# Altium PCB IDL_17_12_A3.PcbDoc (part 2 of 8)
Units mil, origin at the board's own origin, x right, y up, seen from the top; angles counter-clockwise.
Board outline 5119.97 x 10350 mil, 6 copper layers (Top Signal, 3.3 Volt, GND, 5 Volt, Split Plane, Bot Signal), stack 66.2 mil thick; 510 components, 178 nets, 2317 pads, 385 vias.
Unrouted connection lines stored in the file: 1.
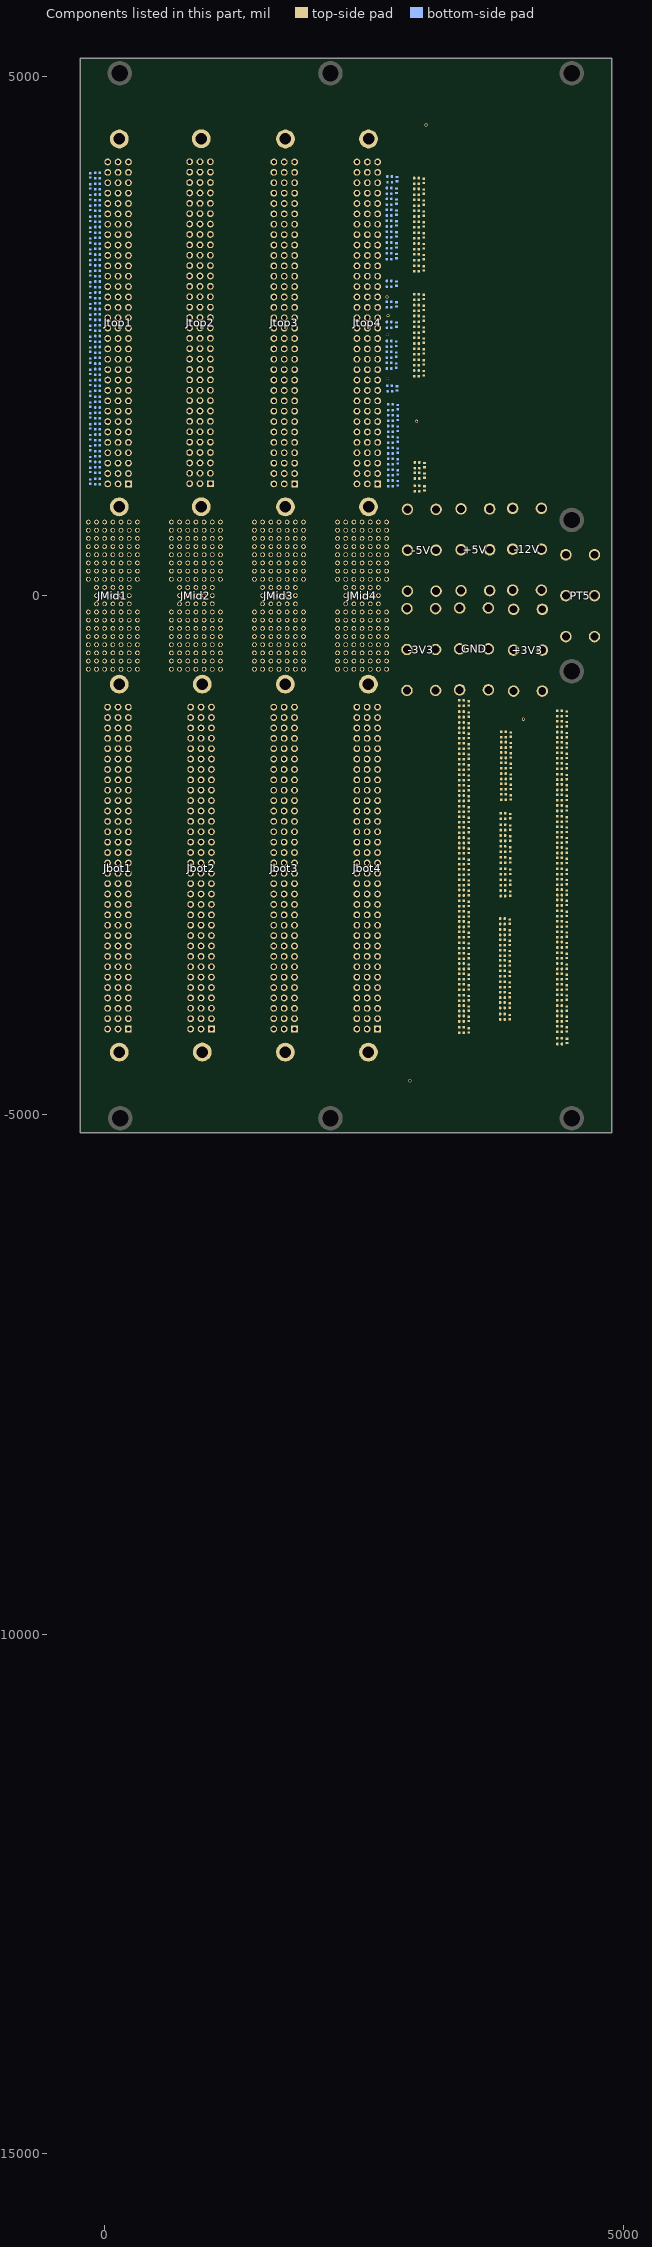
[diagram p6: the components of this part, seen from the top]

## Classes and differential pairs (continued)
component class IDL_17_12_TerB50: CRB_IDL_17_12_TerB50 R1RB_IDL_17_12_TerB50 R2RB_IDL_17_12_TerB50
component class IDL_17_12_TerB51: CRB_IDL_17_12_TerB51 R1RB_IDL_17_12_TerB51 R2RB_IDL_17_12_TerB51
component class IDL_17_12_TerB52: CRB_IDL_17_12_TerB52 R1RB_IDL_17_12_TerB52 R2RB_IDL_17_12_TerB52
component class IDL_17_12_TerB53: CRB_IDL_17_12_TerB53 R1RB_IDL_17_12_TerB53 R2RB_IDL_17_12_TerB53
component class IDL_17_12_TerB54: CRB_IDL_17_12_TerB54 R1RB_IDL_17_12_TerB54 R2RB_IDL_17_12_TerB54
component class IDL_17_12_TerB55: CRB_IDL_17_12_TerB55 R1RB_IDL_17_12_TerB55 R2RB_IDL_17_12_TerB55
component class IDL_17_12_TerB56: CRB_IDL_17_12_TerB56 R1RB_IDL_17_12_TerB56 R2RB_IDL_17_12_TerB56
component class IDL_17_12_TerB57: CRB_IDL_17_12_TerB57 R1RB_IDL_17_12_TerB57 R2RB_IDL_17_12_TerB57
component class IDL_17_12_TerB58: CRB_IDL_17_12_TerB58 R1RB_IDL_17_12_TerB58 R2RB_IDL_17_12_TerB58
component class IDL_17_12_TerB59: CRB_IDL_17_12_TerB59 R1RB_IDL_17_12_TerB59 R2RB_IDL_17_12_TerB59
component class IDL_17_12_TerB60: CRB_IDL_17_12_TerB60 R1RB_IDL_17_12_TerB60 R2RB_IDL_17_12_TerB60
component class IDL_17_12_TerB61: CRB_IDL_17_12_TerB61 R1RB_IDL_17_12_TerB61 R2RB_IDL_17_12_TerB61
component class IDL_17_12_TerB62: CRB_IDL_17_12_TerB62 R1RB_IDL_17_12_TerB62 R2RB_IDL_17_12_TerB62
component class IDL_17_12_TerB63: CRB_IDL_17_12_TerB63 R1RB_IDL_17_12_TerB63 R2RB_IDL_17_12_TerB63
component class IDL_17_12_TerB64: CRB_IDL_17_12_TerB64 R1RB_IDL_17_12_TerB64 R2RB_IDL_17_12_TerB64
component class IDL_17_12_TerB65: CRB_IDL_17_12_TerB65 R1RB_IDL_17_12_TerB65 R2RB_IDL_17_12_TerB65
component class IDL_17_12_TerB66: CRB_IDL_17_12_TerB66 R1RB_IDL_17_12_TerB66 R2RB_IDL_17_12_TerB66
component class IDL_17_12_TerB67: CRB_IDL_17_12_TerB67 R1RB_IDL_17_12_TerB67 R2RB_IDL_17_12_TerB67
component class IDL_17_12_TerB68: CRB_IDL_17_12_TerB68 R1RB_IDL_17_12_TerB68 R2RB_IDL_17_12_TerB68
component class IDL_17_12_TerB69: CRB_IDL_17_12_TerB69 R1RB_IDL_17_12_TerB69 R2RB_IDL_17_12_TerB69
component class IDL_17_12_TerB70: CRB_IDL_17_12_TerB70 R1RB_IDL_17_12_TerB70 R2RB_IDL_17_12_TerB70
component class IDL_17_12_TerB71: CRB_IDL_17_12_TerB71 R1RB_IDL_17_12_TerB71 R2RB_IDL_17_12_TerB71
component class IDL_17_12_TerB72: CRB_IDL_17_12_TerB72 R1RB_IDL_17_12_TerB72 R2RB_IDL_17_12_TerB72
component class IDL_17_12_TerB73: CRB_IDL_17_12_TerB73 R1RB_IDL_17_12_TerB73 R2RB_IDL_17_12_TerB73
component class IDL_17_12_TerB74: CRB_IDL_17_12_TerB74 R1RB_IDL_17_12_TerB74 R2RB_IDL_17_12_TerB74
component class IDL_17_12_TerB75: CRB_IDL_17_12_TerB75 R1RB_IDL_17_12_TerB75 R2RB_IDL_17_12_TerB75
component class IDL_17_12_TerB76: CRB_IDL_17_12_TerB76 R1RB_IDL_17_12_TerB76 R2RB_IDL_17_12_TerB76
component class IDL_17_12_TerB77: CRB_IDL_17_12_TerB77 R1RB_IDL_17_12_TerB77 R2RB_IDL_17_12_TerB77
component class IDL_17_12_TerB78: CRB_IDL_17_12_TerB78 R1RB_IDL_17_12_TerB78 R2RB_IDL_17_12_TerB78
component class IDL_17_12_TerB79: CRB_IDL_17_12_TerB79 R1RB_IDL_17_12_TerB79 R2RB_IDL_17_12_TerB79
component class IDL_17_12_TerB80: CRB_IDL_17_12_TerB80 R1RB_IDL_17_12_TerB80 R2RB_IDL_17_12_TerB80
component class IDL_17_12_TerB81: CRB_IDL_17_12_TerB81 R1RB_IDL_17_12_TerB81 R2RB_IDL_17_12_TerB81
component class IDL_17_12_TerB82: CRB_IDL_17_12_TerB82 R1RB_IDL_17_12_TerB82 R2RB_IDL_17_12_TerB82
component class IDL_17_12_TerB83: CRB_IDL_17_12_TerB83 R1RB_IDL_17_12_TerB83 R2RB_IDL_17_12_TerB83
component class IDL_17_12_TerB84: CRB_IDL_17_12_TerB84 R1RB_IDL_17_12_TerB84 R2RB_IDL_17_12_TerB84
component class IDL_17_12_TerB85: CRB_IDL_17_12_TerB85 R1RB_IDL_17_12_TerB85 R2RB_IDL_17_12_TerB85
component class IDL_17_12_TerB86: CRB_IDL_17_12_TerB86 R1RB_IDL_17_12_TerB86 R2RB_IDL_17_12_TerB86
component class IDL_17_12_TerB87: CRB_IDL_17_12_TerB87 R1RB_IDL_17_12_TerB87 R2RB_IDL_17_12_TerB87
component class IDL_17_12_TerB88: CRB_IDL_17_12_TerB88 R1RB_IDL_17_12_TerB88 R2RB_IDL_17_12_TerB88
component class IDL_17_12_Top: +3V3 +5V -3V3 -5V -12V GND PT5
net class JB[1..89]: JB1 JB2 JB3 JB4 JB5 JB6 JB7 JB8 JB9 JB10 JB11 JB12 JB13 JB14 JB15 JB16 JB17 JB18 JB19 JB20 JB21 JB22 JB23 JB24 JB25 JB26 JB27 JB28 JB29 JB30 JB31 JB32 JB33 JB34 JB35 JB36 JB37 JB38 JB39 JB40 JB41 JB42 JB43 JB44 JB45 JB46 JB47 JB48 JB49 JB50 JB51 JB52 JB53 JB54 JB55 JB56 JB57 JB58 JB59 JB60 JB61 JB62 JB63 JB64 JB65 JB66 JB67 JB68 JB69 JB70 JB71 JB72 JB73 JB74 JB75 JB76 JB77 JB78 JB79 JB80 JB81 JB82 JB83 JB84 JB85 JB86 JB87 JB88 JB89
net class JT[1..72]: JT1 JT2 JT3 JT4 JT5 JT6 JT7 JT8 JT9 JT10 JT11 JT12 JT13 JT14 JT15 JT16 JT17 JT18 JT19 JT20 JT21 JT22 JT23 JT24 JT25 JT26 JT27 JT28 JT29 JT30 JT31 JT32 JT33 JT34 JT35 JT36 JT37 JT38 JT39 JT40 JT41 JT42 JT43 JT44 JT45 JT46 JT47 JT48 JT49 JT50 JT51 JT52 JT53 JT54 JT55 JT56 JT57 JT58 JT59 JT60 JT61 JT62 JT63 JT64 JT65 JT66 JT67 JT68 JT69 JT70 JT71 JT72
channel class IDL_17_12_TerA: IDL_17_12_TerA1 IDL_17_12_TerA2 IDL_17_12_TerA3 IDL_17_12_TerA4 IDL_17_12_TerA5 IDL_17_12_TerA6 IDL_17_12_TerA7 IDL_17_12_TerA8 IDL_17_12_TerA9 IDL_17_12_TerA10 IDL_17_12_TerA11 IDL_17_12_TerA12 IDL_17_12_TerA13 IDL_17_12_TerA14 IDL_17_12_TerA15 IDL_17_12_TerA16 IDL_17_12_TerA17 IDL_17_12_TerA18 IDL_17_12_TerA19 IDL_17_12_TerA20 IDL_17_12_TerA21 IDL_17_12_TerA22 IDL_17_12_TerA23 IDL_17_12_TerA24 IDL_17_12_TerA25 IDL_17_12_TerA26 IDL_17_12_TerA27 IDL_17_12_TerA28 IDL_17_12_TerA29 IDL_17_12_TerA30 IDL_17_12_TerA31 IDL_17_12_TerA32 IDL_17_12_TerA33 IDL_17_12_TerA34 IDL_17_12_TerA35 IDL_17_12_TerA36 IDL_17_12_TerA37 IDL_17_12_TerA38 IDL_17_12_TerA39 IDL_17_12_TerA40 IDL_17_12_TerA41 IDL_17_12_TerA42 IDL_17_12_TerA43 IDL_17_12_TerA44 IDL_17_12_TerA45 IDL_17_12_TerA46 IDL_17_12_TerA47 IDL_17_12_TerA48 IDL_17_12_TerA49 IDL_17_12_TerA50 IDL_17_12_TerA51 IDL_17_12_TerA52 IDL_17_12_TerA53 IDL_17_12_TerA54 IDL_17_12_TerA55 IDL_17_12_TerA56 IDL_17_12_TerA57 IDL_17_12_TerA58 IDL_17_12_TerA59 IDL_17_12_TerA60 IDL_17_12_TerA61 IDL_17_12_TerA62 IDL_17_12_TerA63 IDL_17_12_TerA64 IDL_17_12_TerA65 IDL_17_12_TerA66 IDL_17_12_TerA67 IDL_17_12_TerA68 IDL_17_12_TerA69 IDL_17_12_TerA70 IDL_17_12_TerA71
channel class IDL_17_12_TerB: IDL_17_12_TerB1 IDL_17_12_TerB2 IDL_17_12_TerB3 IDL_17_12_TerB4 IDL_17_12_TerB5 IDL_17_12_TerB6 IDL_17_12_TerB7 IDL_17_12_TerB8 IDL_17_12_TerB9 IDL_17_12_TerB10 IDL_17_12_TerB11 IDL_17_12_TerB12 IDL_17_12_TerB13 IDL_17_12_TerB14 IDL_17_12_TerB15 IDL_17_12_TerB16 IDL_17_12_TerB17 IDL_17_12_TerB18 IDL_17_12_TerB19 IDL_17_12_TerB20 IDL_17_12_TerB21 IDL_17_12_TerB22 IDL_17_12_TerB23 IDL_17_12_TerB24 IDL_17_12_TerB25 IDL_17_12_TerB26 IDL_17_12_TerB27 IDL_17_12_TerB28 IDL_17_12_TerB29 IDL_17_12_TerB30 IDL_17_12_TerB31 IDL_17_12_TerB32 IDL_17_12_TerB33 IDL_17_12_TerB34 IDL_17_12_TerB35 IDL_17_12_TerB36 IDL_17_12_TerB37 IDL_17_12_TerB38 IDL_17_12_TerB39 IDL_17_12_TerB40 IDL_17_12_TerB41 IDL_17_12_TerB42 IDL_17_12_TerB43 IDL_17_12_TerB44 IDL_17_12_TerB45 IDL_17_12_TerB46 IDL_17_12_TerB47 IDL_17_12_TerB48 IDL_17_12_TerB49 IDL_17_12_TerB50 IDL_17_12_TerB51 IDL_17_12_TerB52 IDL_17_12_TerB53 IDL_17_12_TerB54 IDL_17_12_TerB55 IDL_17_12_TerB56 IDL_17_12_TerB57 IDL_17_12_TerB58 IDL_17_12_TerB59 IDL_17_12_TerB60 IDL_17_12_TerB61 IDL_17_12_TerB62 IDL_17_12_TerB63 IDL_17_12_TerB64 IDL_17_12_TerB65 IDL_17_12_TerB66 IDL_17_12_TerB67 IDL_17_12_TerB68 IDL_17_12_TerB69 IDL_17_12_TerB70 IDL_17_12_TerB71 IDL_17_12_TerB72 IDL_17_12_TerB73 IDL_17_12_TerB74 IDL_17_12_TerB75 IDL_17_12_TerB76 IDL_17_12_TerB77 IDL_17_12_TerB78 IDL_17_12_TerB79 IDL_17_12_TerB80 IDL_17_12_TerB81 IDL_17_12_TerB82 IDL_17_12_TerB83 IDL_17_12_TerB84 IDL_17_12_TerB85 IDL_17_12_TerB86 IDL_17_12_TerB87 IDL_17_12_TerB88
component class IDL_17_12_TerB89: CRB_IDL_17_12_TerB89 R1RB_IDL_17_12_TerB89 R2RB_IDL_17_12_TerB89

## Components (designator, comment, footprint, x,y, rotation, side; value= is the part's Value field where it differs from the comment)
+3V3 "*" PowerTap 3938.12,-919.16 r90 top (schematic designator PT2)
+5V "*" PowerTap 3431.95,48.27 r90 top (schematic designator PT7)
-3V3 "*" PowerTap 2911,-912.72 r90 top (schematic designator PT3)
-5V "*" PowerTap 2915.56,43.52 r90 top (schematic designator PT1)
-12V "*" PowerTap 3929.35,53.22 r90 top (schematic designator PT6)
AS "Comment" TPH0.5S 2717.58,2875.93 r0 bottom
CR_IDL_17_12_TerA1 ".1uF" CC0402N1X 2814.85,4010.34 r90 bottom (schematic designator CR)
CR_IDL_17_12_TerA2 ".1uF" CC0402N1X 2809.85,3899.1 r90 bottom (schematic designator CR)
CR_IDL_17_12_TerA3 ".1uF" CC0402N1X 2809.85,3794.1 r90 bottom (schematic designator CR)
CR_IDL_17_12_TerA4 ".1uF" CC0402N1X 2809.85,3689.1 r90 bottom (schematic designator CR)
CR_IDL_17_12_TerA5 ".1uF" CC0402N1X 2809.85,3584.1 r90 bottom (schematic designator CR)
CR_IDL_17_12_TerA6 ".1uF" CC0402N1X 2809.85,3479.1 r90 bottom (schematic designator CR)
CR_IDL_17_12_TerA7 ".1uF" CC0402N1X 2809.85,3374.1 r90 bottom (schematic designator CR)
CR_IDL_17_12_TerA8 ".1uF" CC0402N1X 2809.85,3269.1 r90 bottom (schematic designator CR)
CR_IDL_17_12_TerA9 ".1uF" CC0402N1X 2809.85,3004.1 r90 bottom (schematic designator CR)
CR_IDL_17_12_TerA10 ".1uF" CC0402N1X 2809.85,2804.1 r90 bottom (schematic designator CR)
CR_IDL_17_12_TerA11 ".1uF" CC0402N1X 2809.85,2609.1 r90 bottom (schematic designator CR)
CR_IDL_17_12_TerA12 ".1uF" CC0402N1X 2809.48,2425.89 r90 bottom (schematic designator CR)
CR_IDL_17_12_TerA13 ".1uF" CC0402N1X 2809.48,2320.89 r90 bottom (schematic designator CR)
CR_IDL_17_12_TerA14 ".1uF" CC0402N1X 2809.48,2215.89 r90 bottom (schematic designator CR)
CR_IDL_17_12_TerA15 ".1uF" CC0402N1X 2815.49,1995.95 r90 bottom (schematic designator CR)
CR_IDL_17_12_TerA16 ".1uF" CC0402N1X 2821.19,1815.25 r90 bottom (schematic designator CR)
CR_IDL_17_12_TerA17 ".1uF" CC0402N1X 2821.19,1712.25 r90 bottom (schematic designator CR)
CR_IDL_17_12_TerA18 ".1uF" CC0402N1X 2821.19,1607.25 r90 bottom (schematic designator CR)
CR_IDL_17_12_TerA19 ".1uF" CC0402N1X 2821.19,1502.25 r90 bottom (schematic designator CR)
CR_IDL_17_12_TerA20 ".1uF" CC0402N1X 2821.19,1397.25 r90 bottom (schematic designator CR)
CR_IDL_17_12_TerA21 ".1uF" CC0402N1X 2821.19,1292.25 r90 bottom (schematic designator CR)
CR_IDL_17_12_TerA22 ".1uF" CC0402N1X 2821.19,1187.25 r90 bottom (schematic designator CR)
CR_IDL_17_12_TerA23 ".1uF" CC0402N1X 2821.19,1082.25 r90 bottom (schematic designator CR)
CR_IDL_17_12_TerA24 ".1uF" CC0402N1X 3073.37,3994.79 r90 top (schematic designator CR)
CR_IDL_17_12_TerA25 ".1uF" CC0402N1X 3073.37,3889.79 r90 top (schematic designator CR)
CR_IDL_17_12_TerA26 ".1uF" CC0402N1X 3073.37,3784.79 r90 top (schematic designator CR)
CR_IDL_17_12_TerA27 ".1uF" CC0402N1X 3073.37,3679.79 r90 top (schematic designator CR)
CR_IDL_17_12_TerA28 ".1uF" CC0402N1X 3073.37,3574.79 r90 top (schematic designator CR)
CR_IDL_17_12_TerA29 ".1uF" CC0402N1X 3073.37,3469.79 r90 top (schematic designator CR)
CR_IDL_17_12_TerA30 ".1uF" CC0402N1X 3073.37,3364.79 r90 top (schematic designator CR)
CR_IDL_17_12_TerA31 ".1uF" CC0402N1X 3073.37,3259.79 r90 top (schematic designator CR)
CR_IDL_17_12_TerA32 ".1uF" CC0402N1X 3073.37,3151.79 r90 top (schematic designator CR)
CR_IDL_17_12_TerA33 ".1uF" CC0402N1X 3073.37,2876.79 r90 top (schematic designator CR)
CR_IDL_17_12_TerA34 ".1uF" CC0402N1X 3073.37,2771.79 r90 top (schematic designator CR)
CR_IDL_17_12_TerA35 ".1uF" CC0402N1X 3073.37,2666.79 r90 top (schematic designator CR)
CR_IDL_17_12_TerA36 ".1uF" CC0402N1X 3073.37,2561.79 r90 top (schematic designator CR)
CR_IDL_17_12_TerA37 ".1uF" CC0402N1X 3073.37,2456.79 r90 top (schematic designator CR)
CR_IDL_17_12_TerA38 ".1uF" CC0402N1X 3073.37,2351.79 r90 top (schematic designator CR)
CR_IDL_17_12_TerA39 ".1uF" CC0402N1X 3073.37,2246.79 r90 top (schematic designator CR)
CR_IDL_17_12_TerA40 ".1uF" CC0402N1X 3073.37,2141.79 r90 top (schematic designator CR)
CR_IDL_17_12_TerA41 ".1uF" CC0402N1X 3079.28,1256.26 r90 top (schematic designator CR)
CR_IDL_17_12_TerA42 ".1uF" CC0402N1X 3079.28,1156.26 r90 top (schematic designator CR)
CR_IDL_17_12_TerA43 ".1uF" CC0402N1X 3079.2,1033.29 r90 top (schematic designator CR)
CR_IDL_17_12_TerA44 ".1uF" CC0402N1X -138.88,4046.37 r90 bottom (schematic designator CR)
CR_IDL_17_12_TerA45 ".1uF" CC0402N1X -138.88,3941.37 r90 bottom (schematic designator CR)
CR_IDL_17_12_TerA46 ".1uF" CC0402N1X -138.88,3836.37 r90 bottom (schematic designator CR)
CR_IDL_17_12_TerA47 ".1uF" CC0402N1X -138.88,3733.37 r90 bottom (schematic designator CR)
CR_IDL_17_12_TerA48 ".1uF" CC0402N1X -138.88,3628.37 r90 bottom (schematic designator CR)
CR_IDL_17_12_TerA49 ".1uF" CC0402N1X -138.88,3523.37 r90 bottom (schematic designator CR)
CR_IDL_17_12_TerA50 ".1uF" CC0402N1X -138.88,3418.37 r90 bottom (schematic designator CR)
CR_IDL_17_12_TerA51 ".1uF" CC0402N1X -138.88,3313.37 r90 bottom (schematic designator CR)
CR_IDL_17_12_TerA52 ".1uF" CC0402N1X -138.88,3208.37 r90 bottom (schematic designator CR)
CR_IDL_17_12_TerA53 ".1uF" CC0402N1X -138.88,3103.37 r90 bottom (schematic designator CR)
CR_IDL_17_12_TerA54 ".1uF" CC0402N1X -138.88,2998.37 r90 bottom (schematic designator CR)
CR_IDL_17_12_TerA55 ".1uF" CC0402N1X -138.88,2893.37 r90 bottom (schematic designator CR)
CR_IDL_17_12_TerA56 ".1uF" CC0402N1X -138.88,2788.37 r90 bottom (schematic designator CR)
CR_IDL_17_12_TerA57 ".1uF" CC0402N1X -138.88,2683.37 r90 bottom (schematic designator CR)
CR_IDL_17_12_TerA58 ".1uF" CC0402N1X -138.88,2578.37 r90 bottom (schematic designator CR)
CR_IDL_17_12_TerA59 ".1uF" CC0402N1X -138.88,2473.37 r90 bottom (schematic designator CR)
CR_IDL_17_12_TerA60 ".1uF" CC0402N1X -138.88,2368.37 r90 bottom (schematic designator CR)
CR_IDL_17_12_TerA61 ".1uF" CC0402N1X -138.88,2263.37 r90 bottom (schematic designator CR)
CR_IDL_17_12_TerA62 ".1uF" CC0402N1X -138.88,2155.37 r90 bottom (schematic designator CR)
CR_IDL_17_12_TerA63 ".1uF" CC0402N1X -138.88,2050.37 r90 bottom (schematic designator CR)
CR_IDL_17_12_TerA64 ".1uF" CC0402N1X -138.88,1945.37 r90 bottom (schematic designator CR)
CR_IDL_17_12_TerA65 ".1uF" CC0402N1X -138.88,1840.37 r90 bottom (schematic designator CR)
CR_IDL_17_12_TerA66 ".1uF" CC0402N1X -138.88,1735.37 r90 bottom (schematic designator CR)
CR_IDL_17_12_TerA67 ".1uF" CC0402N1X -138.88,1630.37 r90 bottom (schematic designator CR)
CR_IDL_17_12_TerA68 ".1uF" CC0402N1X -138.88,1525.37 r90 bottom (schematic designator CR)
CR_IDL_17_12_TerA69 ".1uF" CC0402N1X -138.88,1420.37 r90 bottom (schematic designator CR)
CR_IDL_17_12_TerA70 ".1uF" CC0402N1X -138.88,1315.37 r90 bottom (schematic designator CR)
CR_IDL_17_12_TerA71 ".1uF" CC0402N1X -138.88,1210.37 r90 bottom (schematic designator CR)
CR_IDL_17_12_TerA72 ".1uF" CC0402N1X -137.57,1097.91 r90 bottom (schematic designator CR)
CRB_IDL_17_12_TerB1 ".1uF" CC0402N1X 3505.91,-1038.01 r90 top (schematic designator CRB)
CRB_IDL_17_12_TerB2 ".1uF" CC0402N1X 3506.6,-1145.48 r90 top (schematic designator CRB)
CRB_IDL_17_12_TerB3 ".1uF" CC0402N1X 3506.6,-1250.48 r90 top (schematic designator CRB)
CRB_IDL_17_12_TerB4 ".1uF" CC0402N1X 3506.6,-1350.48 r90 top (schematic designator CRB)
CRB_IDL_17_12_TerB5 ".1uF" CC0402N1X 3506.6,-1450.48 r90 top (schematic designator CRB)
CRB_IDL_17_12_TerB6 ".1uF" CC0402N1X 3506.6,-1550.48 r90 top (schematic designator CRB)
CRB_IDL_17_12_TerB7 ".1uF" CC0402N1X 3506.6,-1653.48 r90 top (schematic designator CRB)
CRB_IDL_17_12_TerB8 ".1uF" CC0402N1X 3506.6,-1753.48 r90 top (schematic designator CRB)
CRB_IDL_17_12_TerB9 ".1uF" CC0402N1X 3506.6,-1853.48 r90 top (schematic designator CRB)
CRB_IDL_17_12_TerB10 ".1uF" CC0402N1X 3506.6,-1953.48 r90 top (schematic designator CRB)
CRB_IDL_17_12_TerB11 ".1uF" CC0402N1X 3506.6,-2058.48 r90 top (schematic designator CRB)
CRB_IDL_17_12_TerB12 ".1uF" CC0402N1X 3506.6,-2158.48 r90 top (schematic designator CRB)
CRB_IDL_17_12_TerB13 ".1uF" CC0402N1X 3506.6,-2258.48 r90 top (schematic designator CRB)
CRB_IDL_17_12_TerB14 ".1uF" CC0402N1X 3506.6,-2358.48 r90 top (schematic designator CRB)
CRB_IDL_17_12_TerB15 ".1uF" CC0402N1X 3506.6,-2458.48 r90 top (schematic designator CRB)
CRB_IDL_17_12_TerB16 ".1uF" CC0402N1X 3506.6,-2563.48 r90 top (schematic designator CRB)
CRB_IDL_17_12_TerB17 ".1uF" CC0402N1X 3506.6,-2663.48 r90 top (schematic designator CRB)
CRB_IDL_17_12_TerB18 ".1uF" CC0402N1X 3506.6,-2763.48 r90 top (schematic designator CRB)
CRB_IDL_17_12_TerB19 ".1uF" CC0402N1X 3506.6,-2863.48 r90 top (schematic designator CRB)
CRB_IDL_17_12_TerB20 ".1uF" CC0402N1X 3506.6,-2968.48 r90 top (schematic designator CRB)
CRB_IDL_17_12_TerB21 ".1uF" CC0402N1X 3506.6,-3068.48 r90 top (schematic designator CRB)
CRB_IDL_17_12_TerB22 ".1uF" CC0402N1X 3506.6,-3166.48 r90 top (schematic designator CRB)
CRB_IDL_17_12_TerB23 ".1uF" CC0402N1X 3506.6,-3266.48 r90 top (schematic designator CRB)
CRB_IDL_17_12_TerB24 ".1uF" CC0402N1X 3506.6,-3371.48 r90 top (schematic designator CRB)
CRB_IDL_17_12_TerB25 ".1uF" CC0402N1X 3506.6,-3471.48 r90 top (schematic designator CRB)
CRB_IDL_17_12_TerB26 ".1uF" CC0402N1X 3506.6,-3571.48 r90 top (schematic designator CRB)
CRB_IDL_17_12_TerB27 ".1uF" CC0402N1X 3506.6,-3671.48 r90 top (schematic designator CRB)
CRB_IDL_17_12_TerB28 ".1uF" CC0402N1X 3506.6,-3771.48 r90 top (schematic designator CRB)
CRB_IDL_17_12_TerB29 ".1uF" CC0402N1X 3506.6,-3876.48 r90 top (schematic designator CRB)
CRB_IDL_17_12_TerB30 ".1uF" CC0402N1X 3506.6,-3976.48 r90 top (schematic designator CRB)
CRB_IDL_17_12_TerB31 ".1uF" CC0402N1X 3506.6,-4076.48 r90 top (schematic designator CRB)
CRB_IDL_17_12_TerB32 ".1uF" CC0402N1X 3506.2,-4185.54 r90 top (schematic designator CRB)
CRB_IDL_17_12_TerB33 ".1uF" CC0402N1X 3910.55,-1339.06 r90 top (schematic designator CRB)
CRB_IDL_17_12_TerB34 ".1uF" CC0402N1X 3910.55,-1439.06 r90 top (schematic designator CRB)
CRB_IDL_17_12_TerB35 ".1uF" CC0402N1X 3910.55,-1539.06 r90 top (schematic designator CRB)
CRB_IDL_17_12_TerB36 ".1uF" CC0402N1X 3910.55,-1639.06 r90 top (schematic designator CRB)
CRB_IDL_17_12_TerB37 ".1uF" CC0402N1X 3910.55,-1742.06 r90 top (schematic designator CRB)
CRB_IDL_17_12_TerB38 ".1uF" CC0402N1X 3910.55,-1842.06 r90 top (schematic designator CRB)
CRB_IDL_17_12_TerB39 ".1uF" CC0402N1X 3910.55,-1942.06 r90 top (schematic designator CRB)
CRB_IDL_17_12_TerB40 ".1uF" CC0402N1X 3905.55,-2123.71 r90 top (schematic designator CRB)
CRB_IDL_17_12_TerB41 ".1uF" CC0402N1X 3905.55,-2233.71 r90 top (schematic designator CRB)
CRB_IDL_17_12_TerB42 ".1uF" CC0402N1X 3905.55,-2338.71 r90 top (schematic designator CRB)
CRB_IDL_17_12_TerB43 ".1uF" CC0402N1X 3905.55,-2443.71 r90 top (schematic designator CRB)
CRB_IDL_17_12_TerB44 ".1uF" CC0402N1X 3905.55,-2548.71 r90 top (schematic designator CRB)
CRB_IDL_17_12_TerB45 ".1uF" CC0402N1X 3905.55,-2658.71 r90 top (schematic designator CRB)
CRB_IDL_17_12_TerB46 ".1uF" CC0402N1X 3905.55,-2763.71 r90 top (schematic designator CRB)
CRB_IDL_17_12_TerB47 ".1uF" CC0402N1X 3905.55,-2868.71 r90 top (schematic designator CRB)
CRB_IDL_17_12_TerB48 ".1uF" CC0402N1X 3900.55,-3138.71 r90 top (schematic designator CRB)
CRB_IDL_17_12_TerB49 ".1uF" CC0402N1X 3900.55,-3243.71 r90 top (schematic designator CRB)
CRB_IDL_17_12_TerB50 ".1uF" CC0402N1X 3900.55,-3343.71 r90 top (schematic designator CRB)
CRB_IDL_17_12_TerB51 ".1uF" CC0402N1X 3900.55,-3443.71 r90 top (schematic designator CRB)
CRB_IDL_17_12_TerB52 ".1uF" CC0402N1X 3900.55,-3541.71 r90 top (schematic designator CRB)
CRB_IDL_17_12_TerB53 ".1uF" CC0402N1X 3900.55,-3641.71 r90 top (schematic designator CRB)
CRB_IDL_17_12_TerB54 ".1uF" CC0402N1X 3900.55,-3746.71 r90 top (schematic designator CRB)
CRB_IDL_17_12_TerB55 ".1uF" CC0402N1X 3900.55,-3846.71 r90 top (schematic designator CRB)
CRB_IDL_17_12_TerB56 ".1uF" CC0402N1X 3900.55,-3946.71 r90 top (schematic designator CRB)
CRB_IDL_17_12_TerB57 ".1uF" CC0402N1X 3900.51,-4057.69 r90 top (schematic designator CRB)
CRB_IDL_17_12_TerB58 ".1uF" CC0402N1X 4450.29,-1137.42 r90 top (schematic designator CRB)
CRB_IDL_17_12_TerB59 ".1uF" CC0402N1X 4450.29,-1237.42 r90 top (schematic designator CRB)
CRB_IDL_17_12_TerB60 ".1uF" CC0402N1X 4450.29,-1342.42 r90 top (schematic designator CRB)
CRB_IDL_17_12_TerB61 ".1uF" CC0402N1X 4450.29,-1442.42 r90 top (schematic designator CRB)
CRB_IDL_17_12_TerB62 ".1uF" CC0402N1X 4450.29,-1542.42 r90 top (schematic designator CRB)
CRB_IDL_17_12_TerB63 ".1uF" CC0402N1X 4450.29,-1642.42 r90 top (schematic designator CRB)
CRB_IDL_17_12_TerB64 ".1uF" CC0402N1X 4450.29,-1747.42 r90 top (schematic designator CRB)
CRB_IDL_17_12_TerB65 ".1uF" CC0402N1X 4450.29,-1847.42 r90 top (schematic designator CRB)
CRB_IDL_17_12_TerB66 ".1uF" CC0402N1X 4450.29,-1947.42 r90 top (schematic designator CRB)
CRB_IDL_17_12_TerB67 ".1uF" CC0402N1X 4450.29,-2049.42 r90 top (schematic designator CRB)
CRB_IDL_17_12_TerB68 ".1uF" CC0402N1X 4450.29,-2154.42 r90 top (schematic designator CRB)
CRB_IDL_17_12_TerB69 ".1uF" CC0402N1X 4450.29,-2254.42 r90 top (schematic designator CRB)
CRB_IDL_17_12_TerB70 ".1uF" CC0402N1X 4450.29,-2354.42 r90 top (schematic designator CRB)
CRB_IDL_17_12_TerB71 ".1uF" CC0402N1X 4450.29,-2454.42 r90 top (schematic designator CRB)
CRB_IDL_17_12_TerB72 ".1uF" CC0402N1X 4450.29,-2554.42 r90 top (schematic designator CRB)
CRB_IDL_17_12_TerB73 ".1uF" CC0402N1X 4450.29,-2659.42 r90 top (schematic designator CRB)
CRB_IDL_17_12_TerB74 ".1uF" CC0402N1X 4450.29,-2759.42 r90 top (schematic designator CRB)
CRB_IDL_17_12_TerB75 ".1uF" CC0402N1X 4450.29,-2859.42 r90 top (schematic designator CRB)
CRB_IDL_17_12_TerB76 ".1uF" CC0402N1X 4450.29,-2959.42 r90 top (schematic designator CRB)
CRB_IDL_17_12_TerB77 ".1uF" CC0402N1X 4450.29,-3064.42 r90 top (schematic designator CRB)
CRB_IDL_17_12_TerB78 ".1uF" CC0402N1X 4450.29,-3164.42 r90 top (schematic designator CRB)
CRB_IDL_17_12_TerB79 ".1uF" CC0402N1X 4450.29,-3264.42 r90 top (schematic designator CRB)
CRB_IDL_17_12_TerB80 ".1uF" CC0402N1X 4450.29,-3364.42 r90 top (schematic designator CRB)
CRB_IDL_17_12_TerB81 ".1uF" CC0402N1X 4450.29,-3469.42 r90 top (schematic designator CRB)
CRB_IDL_17_12_TerB82 ".1uF" CC0402N1X 4450.29,-3571.42 r90 top (schematic designator CRB)
CRB_IDL_17_12_TerB83 ".1uF" CC0402N1X 4450.29,-3671.42 r90 top (schematic designator CRB)
CRB_IDL_17_12_TerB84 ".1uF" CC0402N1X 4450.29,-3771.42 r90 top (schematic designator CRB)
CRB_IDL_17_12_TerB85 ".1uF" CC0402N1X 4450.29,-3871.42 r90 top (schematic designator CRB)
CRB_IDL_17_12_TerB86 ".1uF" CC0402N1X 4450.29,-3976.42 r90 top (schematic designator CRB)
CRB_IDL_17_12_TerB87 ".1uF" CC0402N1X 4450.29,-4076.42 r90 top (schematic designator CRB)
CRB_IDL_17_12_TerB88 ".1uF" CC0402N1X 4450.29,-4176.42 r90 top (schematic designator CRB)
CRB_IDL_17_12_TerB89 ".1uF" CC0402N1X 4451.51,-4288.13 r90 top (schematic designator CRB)
DTACK "Comment" TPH0.5S 2729.61,2696.1 r0 bottom
GND "*" PowerTap 3418.77,-906.67 r90 top (schematic designator PT4)
GND "Comment" TPH0.5S 4032.27,-1189.75 r0 top
GND "Comment" TPH0.5S 2938.82,-4671.37 r0 top
GND "Comment" TPH0.5S 3095.22,4533.28 r0 top
GND "Comment" TPH0.5S 3003.96,1679.15 r0 top
Jbot1 "" 0903296x825 128.26,-2623.77 r90 top
Jbot2 "" 0903296x825 928.19,-2623.35 r90 top
Jbot3 "" 0903296x825 1728.19,-2623.77 r90 top
Jbot4 "" 0903296x825 2528.19,-2623.77 r90 top
JMid1 "" "127-Pin Conncector" 74.8,23.74 r90 top
JMid2 "" "127-Pin Conncector" 874.8,23.74 r90 top
JMid3 "" "127-Pin Conncector" 1674.8,23.74 r90 top
JMid4 "" "127-Pin Conncector" 2474.8,23.74 r90 top
Jtop1 "" 0903296x825 129.28,2626.24 r90 top
Jtop2 "" 0903296x825 918.19,2628.35 r90 top
Jtop3 "" 0903296x825 1729.28,2626.24 r90 top
Jtop4 "" 0903296x825 2529.28,2626.24 r90 top
PT5 "*" PowerTap 4440.81,-394.17 r90 top
R1R_IDL_17_12_TerA1 "330R" RC0402N1R 2744.24,4036.92 r0 bottom (schematic designator R1R)
R1R_IDL_17_12_TerA2 "330R" RC0402N1R 2739.24,3925.68 r0 bottom (schematic designator R1R)
R1R_IDL_17_12_TerA3 "330R" RC0402N1R 2739.24,3820.68 r0 bottom (schematic designator R1R)
R1R_IDL_17_12_TerA4 "330R" RC0402N1R 2739.24,3715.68 r0 bottom (schematic designator R1R)
R1R_IDL_17_12_TerA5 "330R" RC0402N1R 2739.24,3610.68 r0 bottom (schematic designator R1R)
R1R_IDL_17_12_TerA6 "330R" RC0402N1R 2739.24,3505.68 r0 bottom (schematic designator R1R)
R1R_IDL_17_12_TerA7 "330R" RC0402N1R 2739.24,3400.68 r0 bottom (schematic designator R1R)
R1R_IDL_17_12_TerA8 "330R" RC0402N1R 2739.24,3295.68 r0 bottom (schematic designator R1R)
R1R_IDL_17_12_TerA9 "330R" RC0402N1R 2739.24,3030.68 r0 bottom (schematic designator R1R)
R1R_IDL_17_12_TerA10 "330R" RC0402N1R 2739.24,2830.68 r0 bottom (schematic designator R1R)
R1R_IDL_17_12_TerA11 "330R" RC0402N1R 2739.24,2635.68 r0 bottom (schematic designator R1R)
R1R_IDL_17_12_TerA12 "330R" RC0402N1R 2738.87,2452.47 r0 bottom (schematic designator R1R)
R1R_IDL_17_12_TerA13 "330R" RC0402N1R 2738.87,2347.47 r0 bottom (schematic designator R1R)
R1R_IDL_17_12_TerA14 "330R" RC0402N1R 2738.87,2242.47 r0 bottom (schematic designator R1R)
R1R_IDL_17_12_TerA15 "330R" RC0402N1R 2744.87,2022.53 r0 bottom (schematic designator R1R)
R1R_IDL_17_12_TerA16 "330R" RC0402N1R 2750.57,1841.82 r0 bottom (schematic designator R1R)
R1R_IDL_17_12_TerA17 "330R" RC0402N1R 2750.57,1738.82 r0 bottom (schematic designator R1R)
R1R_IDL_17_12_TerA18 "330R" RC0402N1R 2750.57,1633.82 r0 bottom (schematic designator R1R)
R1R_IDL_17_12_TerA19 "330R" RC0402N1R 2750.57,1528.82 r0 bottom (schematic designator R1R)
R1R_IDL_17_12_TerA20 "330R" RC0402N1R 2750.57,1423.82 r0 bottom (schematic designator R1R)
R1R_IDL_17_12_TerA21 "330R" RC0402N1R 2750.57,1318.82 r0 bottom (schematic designator R1R)
R1R_IDL_17_12_TerA22 "330R" RC0402N1R 2750.57,1213.82 r0 bottom (schematic designator R1R)
R1R_IDL_17_12_TerA23 "330R" RC0402N1R 2750.57,1108.82 r0 bottom (schematic designator R1R)
R1R_IDL_17_12_TerA24 "330R" RC0402N1R 3002.76,4021.36 r0 top (schematic designator R1R)
R1R_IDL_17_12_TerA25 "330R" RC0402N1R 3002.76,3916.36 r0 top (schematic designator R1R)
R1R_IDL_17_12_TerA26 "330R" RC0402N1R 3002.76,3811.36 r0 top (schematic designator R1R)
R1R_IDL_17_12_TerA27 "330R" RC0402N1R 3002.76,3706.36 r0 top (schematic designator R1R)
R1R_IDL_17_12_TerA28 "330R" RC0402N1R 3002.76,3601.36 r0 top (schematic designator R1R)
R1R_IDL_17_12_TerA29 "330R" RC0402N1R 3002.76,3496.36 r0 top (schematic designator R1R)
R1R_IDL_17_12_TerA30 "330R" RC0402N1R 3002.76,3391.36 r0 top (schematic designator R1R)
R1R_IDL_17_12_TerA31 "330R" RC0402N1R 3002.76,3286.36 r0 top (schematic designator R1R)
R1R_IDL_17_12_TerA32 "330R" RC0402N1R 3002.76,3178.36 r0 top (schematic designator R1R)
R1R_IDL_17_12_TerA33 "330R" RC0402N1R 3002.76,2903.36 r0 top (schematic designator R1R)
R1R_IDL_17_12_TerA34 "330R" RC0402N1R 3002.76,2798.36 r0 top (schematic designator R1R)
R1R_IDL_17_12_TerA35 "330R" RC0402N1R 3002.76,2693.36 r0 top (schematic designator R1R)
R1R_IDL_17_12_TerA36 "330R" RC0402N1R 3002.76,2588.36 r0 top (schematic designator R1R)
R1R_IDL_17_12_TerA37 "330R" RC0402N1R 3002.76,2483.36 r0 top (schematic designator R1R)
R1R_IDL_17_12_TerA38 "330R" RC0402N1R 3002.76,2378.36 r0 top (schematic designator R1R)
R1R_IDL_17_12_TerA39 "330R" RC0402N1R 3002.76,2273.36 r0 top (schematic designator R1R)
R1R_IDL_17_12_TerA40 "330R" RC0402N1R 3002.76,2168.36 r0 top (schematic designator R1R)
R1R_IDL_17_12_TerA41 "330R" RC0402N1R 3008.66,1282.84 r0 top (schematic designator R1R)
R1R_IDL_17_12_TerA42 "330R" RC0402N1R 3008.66,1182.84 r0 top (schematic designator R1R)
R1R_IDL_17_12_TerA43 "330R" RC0402N1R 3008.59,1059.87 r0 top (schematic designator R1R)
R1R_IDL_17_12_TerA44 "330R" RC0402N1R -68.27,4072.95 r180 bottom (schematic designator R1R)
R1R_IDL_17_12_TerA45 "330R" RC0402N1R -68.27,3967.95 r180 bottom (schematic designator R1R)
R1R_IDL_17_12_TerA46 "330R" RC0402N1R -68.27,3862.95 r180 bottom (schematic designator R1R)
R1R_IDL_17_12_TerA47 "330R" RC0402N1R -68.27,3759.95 r180 bottom (schematic designator R1R)
R1R_IDL_17_12_TerA48 "330R" RC0402N1R -68.27,3654.95 r180 bottom (schematic designator R1R)
R1R_IDL_17_12_TerA49 "330R" RC0402N1R -68.27,3549.95 r180 bottom (schematic designator R1R)
R1R_IDL_17_12_TerA50 "330R" RC0402N1R -68.27,3444.95 r180 bottom (schematic designator R1R)
R1R_IDL_17_12_TerA51 "330R" RC0402N1R -68.27,3339.95 r180 bottom (schematic designator R1R)
R1R_IDL_17_12_TerA52 "330R" RC0402N1R -68.27,3234.95 r180 bottom (schematic designator R1R)
R1R_IDL_17_12_TerA53 "330R" RC0402N1R -68.27,3129.95 r180 bottom (schematic designator R1R)
R1R_IDL_17_12_TerA54 "330R" RC0402N1R -68.27,3024.95 r180 bottom (schematic designator R1R)
R1R_IDL_17_12_TerA55 "330R" RC0402N1R -68.27,2919.95 r180 bottom (schematic designator R1R)
R1R_IDL_17_12_TerA56 "330R" RC0402N1R -68.27,2814.95 r180 bottom (schematic designator R1R)
R1R_IDL_17_12_TerA57 "330R" RC0402N1R -68.27,2709.95 r180 bottom (schematic designator R1R)
R1R_IDL_17_12_TerA58 "330R" RC0402N1R -68.27,2604.95 r180 bottom (schematic designator R1R)
R1R_IDL_17_12_TerA59 "330R" RC0402N1R -68.27,2499.95 r180 bottom (schematic designator R1R)
R1R_IDL_17_12_TerA60 "330R" RC0402N1R -68.27,2394.95 r180 bottom (schematic designator R1R)
R1R_IDL_17_12_TerA61 "330R" RC0402N1R -68.27,2289.95 r180 bottom (schematic designator R1R)
R1R_IDL_17_12_TerA62 "330R" RC0402N1R -68.27,2181.95 r180 bottom (schematic designator R1R)
R1R_IDL_17_12_TerA63 "330R" RC0402N1R -68.27,2076.95 r180 bottom (schematic designator R1R)
R1R_IDL_17_12_TerA64 "330R" RC0402N1R -68.27,1971.95 r180 bottom (schematic designator R1R)
R1R_IDL_17_12_TerA65 "330R" RC0402N1R -68.27,1866.95 r180 bottom (schematic designator R1R)
R1R_IDL_17_12_TerA66 "330R" RC0402N1R -68.27,1761.95 r180 bottom (schematic designator R1R)
R1R_IDL_17_12_TerA67 "330R" RC0402N1R -68.27,1656.95 r180 bottom (schematic designator R1R)
R1R_IDL_17_12_TerA68 "330R" RC0402N1R -68.27,1551.95 r180 bottom (schematic designator R1R)
R1R_IDL_17_12_TerA69 "330R" RC0402N1R -68.27,1446.95 r180 bottom (schematic designator R1R)
R1R_IDL_17_12_TerA70 "330R" RC0402N1R -68.27,1341.95 r180 bottom (schematic designator R1R)
R1R_IDL_17_12_TerA71 "330R" RC0402N1R -68.27,1236.95 r180 bottom (schematic designator R1R)
R1R_IDL_17_12_TerA72 "330R" RC0402N1R -68.28,1126.4 r180 bottom (schematic designator R1R)
R1RB_IDL_17_12_TerB1 "330R" RC0402N1R 3435.44,-1008.84 r0 top (schematic designator R1RB)
R1RB_IDL_17_12_TerB2 "330R" RC0402N1R 3436.13,-1116.31 r0 top (schematic designator R1RB)
R1RB_IDL_17_12_TerB3 "330R" RC0402N1R 3436.13,-1221.31 r0 top (schematic designator R1RB)
R1RB_IDL_17_12_TerB4 "330R" RC0402N1R 3436.13,-1321.31 r0 top (schematic designator R1RB)
R1RB_IDL_17_12_TerB5 "330R" RC0402N1R 3436.13,-1421.31 r0 top (schematic designator R1RB)
R1RB_IDL_17_12_TerB6 "330R" RC0402N1R 3436.13,-1521.31 r0 top (schematic designator R1RB)
R1RB_IDL_17_12_TerB7 "330R" RC0402N1R 3436.13,-1624.31 r0 top (schematic designator R1RB)
R1RB_IDL_17_12_TerB8 "330R" RC0402N1R 3436.13,-1724.31 r0 top (schematic designator R1RB)
R1RB_IDL_17_12_TerB9 "330R" RC0402N1R 3436.13,-1824.31 r0 top (schematic designator R1RB)
R1RB_IDL_17_12_TerB10 "330R" RC0402N1R 3436.13,-1924.31 r0 top (schematic designator R1RB)
R1RB_IDL_17_12_TerB11 "330R" RC0402N1R 3436.13,-2029.31 r0 top (schematic designator R1RB)
R1RB_IDL_17_12_TerB12 "330R" RC0402N1R 3436.13,-2129.31 r0 top (schematic designator R1RB)
R1RB_IDL_17_12_TerB13 "330R" RC0402N1R 3436.13,-2229.31 r0 top (schematic designator R1RB)
R1RB_IDL_17_12_TerB14 "330R" RC0402N1R 3436.13,-2329.31 r0 top (schematic designator R1RB)
R1RB_IDL_17_12_TerB15 "330R" RC0402N1R 3436.13,-2429.31 r0 top (schematic designator R1RB)
R1RB_IDL_17_12_TerB16 "330R" RC0402N1R 3436.13,-2534.31 r0 top (schematic designator R1RB)
R1RB_IDL_17_12_TerB17 "330R" RC0402N1R 3436.13,-2634.31 r0 top (schematic designator R1RB)
R1RB_IDL_17_12_TerB18 "330R" RC0402N1R 3436.13,-2734.31 r0 top (schematic designator R1RB)
R1RB_IDL_17_12_TerB19 "330R" RC0402N1R 3436.13,-2834.31 r0 top (schematic designator R1RB)
R1RB_IDL_17_12_TerB20 "330R" RC0402N1R 3436.13,-2939.31 r0 top (schematic designator R1RB)
R1RB_IDL_17_12_TerB21 "330R" RC0402N1R 3436.13,-3039.31 r0 top (schematic designator R1RB)
R1RB_IDL_17_12_TerB22 "330R" RC0402N1R 3436.13,-3137.31 r0 top (schematic designator R1RB)
R1RB_IDL_17_12_TerB23 "330R" RC0402N1R 3436.13,-3237.31 r0 top (schematic designator R1RB)
R1RB_IDL_17_12_TerB24 "330R" RC0402N1R 3436.13,-3342.31 r0 top (schematic designator R1RB)
R1RB_IDL_17_12_TerB25 "330R" RC0402N1R 3436.13,-3442.31 r0 top (schematic designator R1RB)
R1RB_IDL_17_12_TerB26 "330R" RC0402N1R 3436.13,-3542.31 r0 top (schematic designator R1RB)
R1RB_IDL_17_12_TerB27 "330R" RC0402N1R 3436.13,-3642.31 r0 top (schematic designator R1RB)
R1RB_IDL_17_12_TerB28 "330R" RC0402N1R 3436.13,-3742.31 r0 top (schematic designator R1RB)
R1RB_IDL_17_12_TerB29 "330R" RC0402N1R 3436.13,-3847.31 r0 top (schematic designator R1RB)
R1RB_IDL_17_12_TerB30 "330R" RC0402N1R 3436.13,-3947.31 r0 top (schematic designator R1RB)
R1RB_IDL_17_12_TerB31 "330R" RC0402N1R 3436.13,-4047.31 r0 top (schematic designator R1RB)
R1RB_IDL_17_12_TerB32 "330R" RC0402N1R 3435.73,-4156.37 r0 top (schematic designator R1RB)
R1RB_IDL_17_12_TerB33 "330R" RC0402N1R 3840.08,-1309.89 r0 top (schematic designator R1RB)
R1RB_IDL_17_12_TerB34 "330R" RC0402N1R 3840.08,-1409.89 r0 top (schematic designator R1RB)
R1RB_IDL_17_12_TerB35 "330R" RC0402N1R 3840.08,-1509.89 r0 top (schematic designator R1RB)
R1RB_IDL_17_12_TerB36 "330R" RC0402N1R 3840.08,-1609.89 r0 top (schematic designator R1RB)
R1RB_IDL_17_12_TerB37 "330R" RC0402N1R 3840.08,-1712.89 r0 top (schematic designator R1RB)
R1RB_IDL_17_12_TerB38 "330R" RC0402N1R 3840.08,-1812.89 r0 top (schematic designator R1RB)
R1RB_IDL_17_12_TerB39 "330R" RC0402N1R 3840.08,-1912.89 r0 top (schematic designator R1RB)
R1RB_IDL_17_12_TerB40 "330R" RC0402N1R 3835.08,-2094.54 r0 top (schematic designator R1RB)
R1RB_IDL_17_12_TerB41 "330R" RC0402N1R 3835.08,-2204.54 r0 top (schematic designator R1RB)
R1RB_IDL_17_12_TerB42 "330R" RC0402N1R 3835.08,-2309.54 r0 top (schematic designator R1RB)
R1RB_IDL_17_12_TerB43 "330R" RC0402N1R 3835.08,-2414.54 r0 top (schematic designator R1RB)
R1RB_IDL_17_12_TerB44 "330R" RC0402N1R 3835.08,-2519.54 r0 top (schematic designator R1RB)
R1RB_IDL_17_12_TerB45 "330R" RC0402N1R 3835.08,-2629.54 r0 top (schematic designator R1RB)
R1RB_IDL_17_12_TerB46 "330R" RC0402N1R 3835.08,-2734.54 r0 top (schematic designator R1RB)
R1RB_IDL_17_12_TerB47 "330R" RC0402N1R 3835.08,-2839.54 r0 top (schematic designator R1RB)
R1RB_IDL_17_12_TerB48 "330R" RC0402N1R 3830.08,-3109.54 r0 top (schematic designator R1RB)
R1RB_IDL_17_12_TerB49 "330R" RC0402N1R 3830.08,-3214.54 r0 top (schematic designator R1RB)
R1RB_IDL_17_12_TerB50 "330R" RC0402N1R 3830.08,-3314.54 r0 top (schematic designator R1RB)
R1RB_IDL_17_12_TerB51 "330R" RC0402N1R 3830.08,-3414.54 r0 top (schematic designator R1RB)
R1RB_IDL_17_12_TerB52 "330R" RC0402N1R 3830.08,-3512.54 r0 top (schematic designator R1RB)
R1RB_IDL_17_12_TerB53 "330R" RC0402N1R 3830.08,-3612.54 r0 top (schematic designator R1RB)
R1RB_IDL_17_12_TerB54 "330R" RC0402N1R 3830.08,-3717.54 r0 top (schematic designator R1RB)
R1RB_IDL_17_12_TerB55 "330R" RC0402N1R 3830.08,-3817.54 r0 top (schematic designator R1RB)
R1RB_IDL_17_12_TerB56 "330R" RC0402N1R 3830.08,-3917.54 r0 top (schematic designator R1RB)
R1RB_IDL_17_12_TerB57 "330R" RC0402N1R 3830.04,-4028.52 r0 top (schematic designator R1RB)
R1RB_IDL_17_12_TerB58 "330R" RC0402N1R 4379.81,-1108.25 r0 top (schematic designator R1RB)
R1RB_IDL_17_12_TerB59 "330R" RC0402N1R 4379.81,-1208.25 r0 top (schematic designator R1RB)
R1RB_IDL_17_12_TerB60 "330R" RC0402N1R 4379.81,-1313.25 r0 top (schematic designator R1RB)
R1RB_IDL_17_12_TerB61 "330R" RC0402N1R 4379.81,-1413.25 r0 top (schematic designator R1RB)
R1RB_IDL_17_12_TerB62 "330R" RC0402N1R 4379.81,-1513.25 r0 top (schematic designator R1RB)
R1RB_IDL_17_12_TerB63 "330R" RC0402N1R 4379.81,-1613.25 r0 top (schematic designator R1RB)
R1RB_IDL_17_12_TerB64 "330R" RC0402N1R 4379.81,-1718.25 r0 top (schematic designator R1RB)
R1RB_IDL_17_12_TerB65 "330R" RC0402N1R 4379.81,-1818.25 r0 top (schematic designator R1RB)
R1RB_IDL_17_12_TerB66 "330R" RC0402N1R 4379.81,-1918.25 r0 top (schematic designator R1RB)
R1RB_IDL_17_12_TerB67 "330R" RC0402N1R 4379.81,-2020.25 r0 top (schematic designator R1RB)
R1RB_IDL_17_12_TerB68 "330R" RC0402N1R 4379.81,-2125.25 r0 top (schematic designator R1RB)
R1RB_IDL_17_12_TerB69 "330R" RC0402N1R 4379.81,-2225.25 r0 top (schematic designator R1RB)
R1RB_IDL_17_12_TerB70 "330R" RC0402N1R 4379.81,-2325.25 r0 top (schematic designator R1RB)
R1RB_IDL_17_12_TerB71 "330R" RC0402N1R 4379.81,-2425.25 r0 top (schematic designator R1RB)
R1RB_IDL_17_12_TerB72 "330R" RC0402N1R 4379.81,-2525.25 r0 top (schematic designator R1RB)
R1RB_IDL_17_12_TerB73 "330R" RC0402N1R 4379.81,-2630.25 r0 top (schematic designator R1RB)
R1RB_IDL_17_12_TerB74 "330R" RC0402N1R 4379.81,-2730.25 r0 top (schematic designator R1RB)
R1RB_IDL_17_12_TerB75 "330R" RC0402N1R 4379.81,-2830.25 r0 top (schematic designator R1RB)
R1RB_IDL_17_12_TerB76 "330R" RC0402N1R 4379.81,-2930.25 r0 top (schematic designator R1RB)
R1RB_IDL_17_12_TerB77 "330R" RC0402N1R 4379.81,-3035.25 r0 top (schematic designator R1RB)
R1RB_IDL_17_12_TerB78 "330R" RC0402N1R 4379.81,-3135.25 r0 top (schematic designator R1RB)
R1RB_IDL_17_12_TerB79 "330R" RC0402N1R 4379.81,-3235.25 r0 top (schematic designator R1RB)
R1RB_IDL_17_12_TerB80 "330R" RC0402N1R 4379.81,-3335.25 r0 top (schematic designator R1RB)
R1RB_IDL_17_12_TerB81 "330R" RC0402N1R 4379.81,-3440.25 r0 top (schematic designator R1RB)
R1RB_IDL_17_12_TerB82 "330R" RC0402N1R 4379.81,-3542.25 r0 top (schematic designator R1RB)
R1RB_IDL_17_12_TerB83 "330R" RC0402N1R 4379.81,-3642.25 r0 top (schematic designator R1RB)
R1RB_IDL_17_12_TerB84 "330R" RC0402N1R 4379.81,-3742.25 r0 top (schematic designator R1RB)
R1RB_IDL_17_12_TerB85 "330R" RC0402N1R 4379.81,-3842.25 r0 top (schematic designator R1RB)
R1RB_IDL_17_12_TerB86 "330R" RC0402N1R 4379.81,-3947.25 r0 top (schematic designator R1RB)
R1RB_IDL_17_12_TerB87 "330R" RC0402N1R 4379.81,-4047.25 r0 top (schematic designator R1RB)
R1RB_IDL_17_12_TerB88 "330R" RC0402N1R 4379.81,-4147.25 r0 top (schematic designator R1RB)
R1RB_IDL_17_12_TerB89 "330R" RC0402N1R 4381.76,-4262.25 r0 top (schematic designator R1RB)
R2R_IDL_17_12_TerA1 "470R" RC0402N1R 2745.11,3981.9 r180 bottom (schematic designator R2R)
R2R_IDL_17_12_TerA2 "470R" RC0402N1R 2740.11,3870.66 r180 bottom (schematic designator R2R)
R2R_IDL_17_12_TerA3 "470R" RC0402N1R 2740.11,3765.66 r180 bottom (schematic designator R2R)
R2R_IDL_17_12_TerA4 "470R" RC0402N1R 2740.11,3660.66 r180 bottom (schematic designator R2R)
R2R_IDL_17_12_TerA5 "470R" RC0402N1R 2740.11,3555.66 r180 bottom (schematic designator R2R)
R2R_IDL_17_12_TerA6 "470R" RC0402N1R 2740.11,3450.66 r180 bottom (schematic designator R2R)
R2R_IDL_17_12_TerA7 "470R" RC0402N1R 2740.11,3345.66 r180 bottom (schematic designator R2R)
R2R_IDL_17_12_TerA8 "470R" RC0402N1R 2740.11,3240.66 r180 bottom (schematic designator R2R)
R2R_IDL_17_12_TerA9 "470R" RC0402N1R 2740.11,2975.66 r180 bottom (schematic designator R2R)
R2R_IDL_17_12_TerA10 "470R" RC0402N1R 2740.11,2775.66 r180 bottom (schematic designator R2R)
R2R_IDL_17_12_TerA11 "470R" RC0402N1R 2740.11,2580.66 r180 bottom (schematic designator R2R)
R2R_IDL_17_12_TerA12 "470R" RC0402N1R 2739.74,2397.45 r180 bottom (schematic designator R2R)
R2R_IDL_17_12_TerA13 "470R" RC0402N1R 2739.74,2292.45 r180 bottom (schematic designator R2R)
R2R_IDL_17_12_TerA14 "470R" RC0402N1R 2739.74,2187.45 r180 bottom (schematic designator R2R)
R2R_IDL_17_12_TerA15 "470R" RC0402N1R 2745.75,1967.51 r180 bottom (schematic designator R2R)
R2R_IDL_17_12_TerA16 "470R" RC0402N1R 2751.45,1786.8 r180 bottom (schematic designator R2R)
R2R_IDL_17_12_TerA17 "470R" RC0402N1R 2751.45,1683.8 r180 bottom (schematic designator R2R)
R2R_IDL_17_12_TerA18 "470R" RC0402N1R 2751.45,1578.8 r180 bottom (schematic designator R2R)
R2R_IDL_17_12_TerA19 "470R" RC0402N1R 2751.45,1473.8 r180 bottom (schematic designator R2R)
R2R_IDL_17_12_TerA20 "470R" RC0402N1R 2751.45,1368.8 r180 bottom (schematic designator R2R)
R2R_IDL_17_12_TerA21 "470R" RC0402N1R 2751.45,1263.8 r180 bottom (schematic designator R2R)
R2R_IDL_17_12_TerA22 "470R" RC0402N1R 2751.45,1158.8 r180 bottom (schematic designator R2R)
R2R_IDL_17_12_TerA23 "470R" RC0402N1R 2751.45,1053.8 r180 bottom (schematic designator R2R)
R2R_IDL_17_12_TerA24 "470R" RC0402N1R 3003.64,3966.34 r180 top (schematic designator R2R)
R2R_IDL_17_12_TerA25 "470R" RC0402N1R 3003.64,3861.34 r180 top (schematic designator R2R)
R2R_IDL_17_12_TerA26 "470R" RC0402N1R 3003.64,3756.34 r180 top (schematic designator R2R)
R2R_IDL_17_12_TerA27 "470R" RC0402N1R 3003.64,3651.34 r180 top (schematic designator R2R)
R2R_IDL_17_12_TerA28 "470R" RC0402N1R 3003.64,3546.34 r180 top (schematic designator R2R)
R2R_IDL_17_12_TerA29 "470R" RC0402N1R 3003.64,3441.34 r180 top (schematic designator R2R)
R2R_IDL_17_12_TerA30 "470R" RC0402N1R 3003.64,3336.34 r180 top (schematic designator R2R)
R2R_IDL_17_12_TerA31 "470R" RC0402N1R 3003.64,3231.34 r180 top (schematic designator R2R)
R2R_IDL_17_12_TerA32 "470R" RC0402N1R 3003.64,3123.34 r180 top (schematic designator R2R)
R2R_IDL_17_12_TerA33 "470R" RC0402N1R 3003.64,2848.34 r180 top (schematic designator R2R)
R2R_IDL_17_12_TerA34 "470R" RC0402N1R 3003.64,2743.34 r180 top (schematic designator R2R)
R2R_IDL_17_12_TerA35 "470R" RC0402N1R 3003.64,2638.34 r180 top (schematic designator R2R)
R2R_IDL_17_12_TerA36 "470R" RC0402N1R 3003.64,2533.34 r180 top (schematic designator R2R)
R2R_IDL_17_12_TerA37 "470R" RC0402N1R 3003.64,2428.34 r180 top (schematic designator R2R)
R2R_IDL_17_12_TerA38 "470R" RC0402N1R 3003.64,2323.34 r180 top (schematic designator R2R)
R2R_IDL_17_12_TerA39 "470R" RC0402N1R 3003.64,2218.34 r180 top (schematic designator R2R)
R2R_IDL_17_12_TerA40 "470R" RC0402N1R 3003.64,2113.34 r180 top (schematic designator R2R)
R2R_IDL_17_12_TerA41 "470R" RC0402N1R 3009.54,1227.82 r180 top (schematic designator R2R)
R2R_IDL_17_12_TerA42 "470R" RC0402N1R 3009.54,1127.82 r180 top (schematic designator R2R)
R2R_IDL_17_12_TerA43 "470R" RC0402N1R 3009.47,1004.85 r180 top (schematic designator R2R)
R2R_IDL_17_12_TerA44 "470R" RC0402N1R -69.15,4017.93 r0 bottom (schematic designator R2R)
R2R_IDL_17_12_TerA45 "470R" RC0402N1R -69.15,3912.93 r0 bottom (schematic designator R2R)
R2R_IDL_17_12_TerA46 "470R" RC0402N1R -69.15,3807.93 r0 bottom (schematic designator R2R)
R2R_IDL_17_12_TerA47 "470R" RC0402N1R -69.15,3704.93 r0 bottom (schematic designator R2R)
R2R_IDL_17_12_TerA48 "470R" RC0402N1R -69.15,3599.93 r0 bottom (schematic designator R2R)
R2R_IDL_17_12_TerA49 "470R" RC0402N1R -69.15,3494.93 r0 bottom (schematic designator R2R)
R2R_IDL_17_12_TerA50 "470R" RC0402N1R -69.15,3389.93 r0 bottom (schematic designator R2R)
R2R_IDL_17_12_TerA51 "470R" RC0402N1R -69.15,3284.93 r0 bottom (schematic designator R2R)
R2R_IDL_17_12_TerA52 "470R" RC0402N1R -69.15,3179.93 r0 bottom (schematic designator R2R)
R2R_IDL_17_12_TerA53 "470R" RC0402N1R -69.15,3074.93 r0 bottom (schematic designator R2R)
R2R_IDL_17_12_TerA54 "470R" RC0402N1R -69.15,2969.93 r0 bottom (schematic designator R2R)
R2R_IDL_17_12_TerA55 "470R" RC0402N1R -69.15,2864.93 r0 bottom (schematic designator R2R)
R2R_IDL_17_12_TerA56 "470R" RC0402N1R -69.15,2759.93 r0 bottom (schematic designator R2R)
R2R_IDL_17_12_TerA57 "470R" RC0402N1R -69.15,2654.93 r0 bottom (schematic designator R2R)
R2R_IDL_17_12_TerA58 "470R" RC0402N1R -69.15,2549.93 r0 bottom (schematic designator R2R)
R2R_IDL_17_12_TerA59 "470R" RC0402N1R -69.15,2444.93 r0 bottom (schematic designator R2R)
R2R_IDL_17_12_TerA60 "470R" RC0402N1R -69.15,2339.93 r0 bottom (schematic designator R2R)
R2R_IDL_17_12_TerA61 "470R" RC0402N1R -69.15,2234.93 r0 bottom (schematic designator R2R)
R2R_IDL_17_12_TerA62 "470R" RC0402N1R -69.15,2126.93 r0 bottom (schematic designator R2R)
R2R_IDL_17_12_TerA63 "470R" RC0402N1R -69.15,2021.93 r0 bottom (schematic designator R2R)
R2R_IDL_17_12_TerA64 "470R" RC0402N1R -69.15,1916.93 r0 bottom (schematic designator R2R)
R2R_IDL_17_12_TerA65 "470R" RC0402N1R -69.15,1811.93 r0 bottom (schematic designator R2R)
R2R_IDL_17_12_TerA66 "470R" RC0402N1R -69.15,1706.93 r0 bottom (schematic designator R2R)
R2R_IDL_17_12_TerA67 "470R" RC0402N1R -69.15,1601.93 r0 bottom (schematic designator R2R)
R2R_IDL_17_12_TerA68 "470R" RC0402N1R -69.15,1496.93 r0 bottom (schematic designator R2R)
R2R_IDL_17_12_TerA69 "470R" RC0402N1R -69.15,1391.93 r0 bottom (schematic designator R2R)
R2R_IDL_17_12_TerA70 "470R" RC0402N1R -69.15,1286.93 r0 bottom (schematic designator R2R)
R2R_IDL_17_12_TerA71 "470R" RC0402N1R -69.15,1181.93 r0 bottom (schematic designator R2R)
R2R_IDL_17_12_TerA72 "470R" RC0402N1R -68.02,1071.89 r0 bottom (schematic designator R2R)
R2RB_IDL_17_12_TerB1 "470R" RC0402N1R 3435.95,-1061.69 r180 top (schematic designator R2RB)
R2RB_IDL_17_12_TerB2 "470R" RC0402N1R 3436.64,-1169.17 r180 top (schematic designator R2RB)
R2RB_IDL_17_12_TerB3 "470R" RC0402N1R 3436.64,-1274.17 r180 top (schematic designator R2RB)
R2RB_IDL_17_12_TerB4 "470R" RC0402N1R 3436.64,-1374.17 r180 top (schematic designator R2RB)
R2RB_IDL_17_12_TerB5 "470R" RC0402N1R 3436.64,-1474.17 r180 top (schematic designator R2RB)
R2RB_IDL_17_12_TerB6 "470R" RC0402N1R 3436.64,-1574.17 r180 top (schematic designator R2RB)
R2RB_IDL_17_12_TerB7 "470R" RC0402N1R 3436.64,-1677.17 r180 top (schematic designator R2RB)
R2RB_IDL_17_12_TerB8 "470R" RC0402N1R 3436.64,-1777.17 r180 top (schematic designator R2RB)
R2RB_IDL_17_12_TerB9 "470R" RC0402N1R 3436.64,-1877.17 r180 top (schematic designator R2RB)
R2RB_IDL_17_12_TerB10 "470R" RC0402N1R 3436.64,-1977.17 r180 top (schematic designator R2RB)
R2RB_IDL_17_12_TerB11 "470R" RC0402N1R 3436.64,-2082.17 r180 top (schematic designator R2RB)
R2RB_IDL_17_12_TerB12 "470R" RC0402N1R 3436.64,-2182.17 r180 top (schematic designator R2RB)
R2RB_IDL_17_12_TerB13 "470R" RC0402N1R 3436.64,-2282.17 r180 top (schematic designator R2RB)
R2RB_IDL_17_12_TerB14 "470R" RC0402N1R 3436.64,-2382.17 r180 top (schematic designator R2RB)
R2RB_IDL_17_12_TerB15 "470R" RC0402N1R 3436.64,-2482.17 r180 top (schematic designator R2RB)
R2RB_IDL_17_12_TerB16 "470R" RC0402N1R 3436.64,-2587.17 r180 top (schematic designator R2RB)
R2RB_IDL_17_12_TerB17 "470R" RC0402N1R 3436.64,-2687.17 r180 top (schematic designator R2RB)
R2RB_IDL_17_12_TerB18 "470R" RC0402N1R 3436.64,-2787.17 r180 top (schematic designator R2RB)
R2RB_IDL_17_12_TerB19 "470R" RC0402N1R 3436.64,-2887.17 r180 top (schematic designator R2RB)
R2RB_IDL_17_12_TerB20 "470R" RC0402N1R 3436.64,-2992.17 r180 top (schematic designator R2RB)
R2RB_IDL_17_12_TerB21 "470R" RC0402N1R 3436.64,-3092.17 r180 top (schematic designator R2RB)
R2RB_IDL_17_12_TerB22 "470R" RC0402N1R 3436.64,-3190.17 r180 top (schematic designator R2RB)
R2RB_IDL_17_12_TerB23 "470R" RC0402N1R 3436.64,-3290.17 r180 top (schematic designator R2RB)
R2RB_IDL_17_12_TerB24 "470R" RC0402N1R 3436.64,-3395.17 r180 top (schematic designator R2RB)
R2RB_IDL_17_12_TerB25 "470R" RC0402N1R 3436.64,-3495.17 r180 top (schematic designator R2RB)
R2RB_IDL_17_12_TerB26 "470R" RC0402N1R 3436.64,-3595.17 r180 top (schematic designator R2RB)
R2RB_IDL_17_12_TerB27 "470R" RC0402N1R 3436.64,-3695.17 r180 top (schematic designator R2RB)
R2RB_IDL_17_12_TerB28 "470R" RC0402N1R 3436.64,-3795.17 r180 top (schematic designator R2RB)
R2RB_IDL_17_12_TerB29 "470R" RC0402N1R 3436.64,-3900.17 r180 top (schematic designator R2RB)
R2RB_IDL_17_12_TerB30 "470R" RC0402N1R 3436.64,-4000.17 r180 top (schematic designator R2RB)
R2RB_IDL_17_12_TerB31 "470R" RC0402N1R 3436.64,-4100.17 r180 top (schematic designator R2RB)
R2RB_IDL_17_12_TerB32 "470R" RC0402N1R 3436.24,-4209.23 r180 top (schematic designator R2RB)
R2RB_IDL_17_12_TerB33 "470R" RC0402N1R 3840.59,-1362.75 r180 top (schematic designator R2RB)
R2RB_IDL_17_12_TerB34 "470R" RC0402N1R 3840.59,-1462.75 r180 top (schematic designator R2RB)
R2RB_IDL_17_12_TerB35 "470R" RC0402N1R 3840.59,-1562.75 r180 top (schematic designator R2RB)
R2RB_IDL_17_12_TerB36 "470R" RC0402N1R 3840.59,-1662.75 r180 top (schematic designator R2RB)
R2RB_IDL_17_12_TerB37 "470R" RC0402N1R 3840.59,-1765.75 r180 top (schematic designator R2RB)
R2RB_IDL_17_12_TerB38 "470R" RC0402N1R 3840.59,-1865.75 r180 top (schematic designator R2RB)
R2RB_IDL_17_12_TerB39 "470R" RC0402N1R 3840.59,-1965.75 r180 top (schematic designator R2RB)
R2RB_IDL_17_12_TerB40 "470R" RC0402N1R 3835.59,-2147.4 r180 top (schematic designator R2RB)
R2RB_IDL_17_12_TerB41 "470R" RC0402N1R 3835.59,-2257.4 r180 top (schematic designator R2RB)
R2RB_IDL_17_12_TerB42 "470R" RC0402N1R 3835.59,-2362.4 r180 top (schematic designator R2RB)
R2RB_IDL_17_12_TerB43 "470R" RC0402N1R 3835.59,-2467.4 r180 top (schematic designator R2RB)
R2RB_IDL_17_12_TerB44 "470R" RC0402N1R 3835.59,-2572.4 r180 top (schematic designator R2RB)
R2RB_IDL_17_12_TerB45 "470R" RC0402N1R 3835.59,-2682.4 r180 top (schematic designator R2RB)
R2RB_IDL_17_12_TerB46 "470R" RC0402N1R 3835.59,-2787.4 r180 top (schematic designator R2RB)
R2RB_IDL_17_12_TerB47 "470R" RC0402N1R 3835.59,-2892.4 r180 top (schematic designator R2RB)
R2RB_IDL_17_12_TerB48 "470R" RC0402N1R 3830.59,-3162.4 r180 top (schematic designator R2RB)
R2RB_IDL_17_12_TerB49 "470R" RC0402N1R 3830.59,-3267.4 r180 top (schematic designator R2RB)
